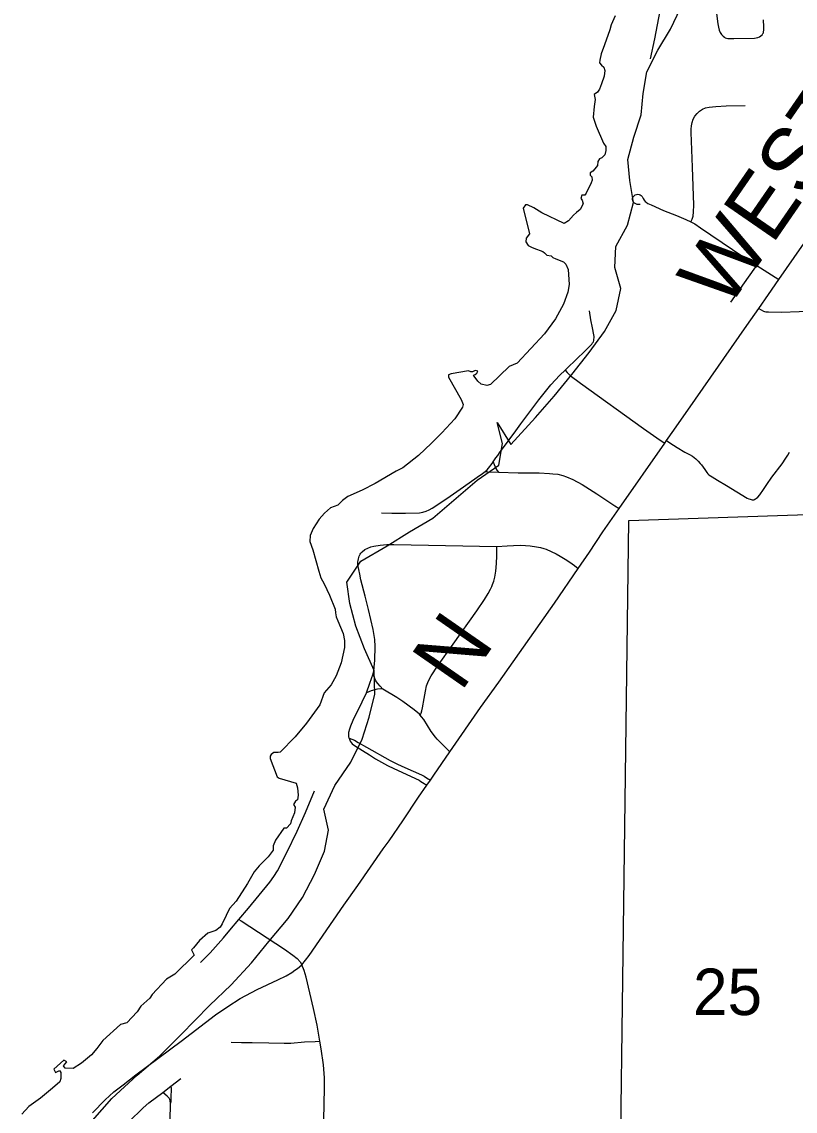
# Model space of a CAD drawing. Extents: x 63.4 to 97.4, y 0.4 to 22.4.
# Drawn here: x 67.176 to 67.874, y 18.029 to 19.011 of the extents above; entities that cross this region are included whole.
import ezdxf

# ---------------------------------------------------------------- set-up
doc = ezdxf.new("R2010")
doc.units = 0
for name, color, linetype in [('GM_X_County_Road', 7, 'Continuous'), ('GM_X_County_Road_Text', 7, 'Continuous'), ('GM_X_Major_Lake', 7, 'Continuous'), ('GM_X_Section', 7, 'Continuous'), ('GM_X_Section_Text', 7, 'Continuous'), ('GM_X_Township_Road', 7, 'Continuous'), ('SH_Cut_Line', 7, 'Continuous')]:
    doc.layers.add(name, color=color, linetype=linetype)

msp = doc.modelspace()

# ---------------------------------------------------------------- linework, layer by layer
at = {"layer": 'GM_X_County_Road'}
for p, q in [((67.71491, 18.57238), (67.75618, 18.63125)), ((67.75618, 18.63125), (67.75785, 18.63363))]:
    msp.add_line(p, q, dxfattribs=at)
for points in [[(67.71154, 19.0165), (67.70789, 19.00859), (67.70659, 19.00381), (67.70172, 18.99034), (67.69886, 18.98243), (67.69747, 18.97661), (67.69738, 18.9741), (67.69903, 18.97201), (67.70129, 18.97018), (67.70216, 18.96723), (67.70137, 18.96219), (67.69912, 18.95532), (67.69738, 18.95055), (67.69538, 18.94776), (67.69249, 18.94562), (67.6933, 18.94116), (67.6926, 18.93473), (67.69147, 18.92518), (67.69425, 18.91718), (67.70085, 18.9018), (67.70303, 18.89884), (67.70303, 18.89511), (67.70198, 18.89129), (67.69946, 18.88859), (67.69738, 18.88763), (67.69573, 18.88529), (67.69538, 18.88164), (67.69321, 18.87868), (67.69138, 18.87642), (67.68886, 18.87495), (67.68886, 18.87304), (67.69043, 18.87147), (67.69077, 18.86843), (67.68973, 18.86608), (67.68521, 18.8567), (67.68417, 18.85479), (67.68139, 18.85479), (67.68035, 18.85184), (67.68156, 18.85044), (67.68261, 18.84697), (67.67982, 18.84193), (67.67653, 18.83932), (67.67392, 18.83672), (67.6694, 18.83167), (67.6654, 18.82942), (67.64541, 18.83897), (67.63812, 18.84349), (67.63238, 18.84627), (67.63047, 18.84627), (67.62856, 18.84332), (67.63429, 18.82003), (67.63117, 18.81621), (67.63082, 18.81291), (67.63307, 18.8096), (67.63655, 18.80787), (67.64055, 18.8063), (67.64385, 18.80508), (67.64628, 18.80421), (67.64767, 18.80283), (67.64993, 18.80091), (67.65376, 18.80022), (67.65532, 18.79865), (67.65793, 18.79744), (67.66488, 18.79483), (67.66696, 18.79258), (67.66905, 18.78788), (67.67009, 18.77433), (67.66888, 18.76737), (67.66471, 18.75677), (67.65758, 18.74356), (67.64767, 18.72984), (67.62317, 18.70359), (67.61582, 18.70044), (67.59884, 18.6843), (67.59571, 18.68326), (67.59067, 18.68465), (67.58754, 18.68726), (67.58424, 18.6916), (67.58354, 18.69265), (67.58528, 18.69334), (67.58668, 18.69455), (67.58754, 18.69629), (67.58528, 18.69699), (67.58285, 18.69577), (67.58111, 18.69577), (67.57903, 18.69664), (67.56356, 18.69386), (67.56113, 18.69282), (67.56096, 18.69073), (67.57259, 18.67058), (67.57433, 18.66605), (67.57364, 18.6638), (67.56686, 18.65337), (67.55522, 18.64051), (67.54566, 18.6313), (67.53419, 18.62018), (67.51977, 18.60923), (67.51386, 18.6061), (67.49492, 18.59497), (67.48327, 18.58906), (67.47041, 18.58333), (67.46537, 18.57968), (67.4612, 18.57534), (67.45477, 18.5729), (67.44938, 18.56838), (67.44434, 18.56282), (67.43896, 18.55431), (67.43635, 18.54805), (67.436, 18.54284), (67.43878, 18.53519), (67.44417, 18.51608), (67.4459, 18.50982), (67.44904, 18.50443), (67.4539, 18.49418), (67.45877, 18.48184), (67.45915, 18.47853), (67.4599, 18.47471), (67.4612, 18.47124), (67.46607, 18.45977), (67.46728, 18.45334), (67.46728, 18.44725), (67.46415, 18.43335), (67.45981, 18.42171), (67.45529, 18.41354), (67.44904, 18.40642), (67.44504, 18.39547), (67.43305, 18.37896), (67.42279, 18.36662), (67.40924, 18.35271), (67.40732, 18.35254), (67.40368, 18.35254), (67.40124, 18.35063), (67.4002, 18.34907), (67.4002, 18.34715), (67.40646, 18.33047), (67.40837, 18.32942), (67.42366, 18.32491), (67.42488, 18.32074), (67.42557, 18.31413), (67.42488, 18.30979), (67.42314, 18.30857), (67.4214, 18.30562), (67.42279, 18.30318), (67.4221, 18.29797), (67.41914, 18.29084), (67.41845, 18.28807), (67.41497, 18.28442), (67.41271, 18.28442), (67.40509, 18.27356), (67.40298, 18.26826), (67.40281, 18.26443), (67.39846, 18.25852), (67.39045, 18.25034), (67.38577, 18.24497), (67.37965, 18.23449), (67.36944, 18.21838), (67.3637, 18.21195), (67.36058, 18.20569), (67.35693, 18.19804), (67.35519, 18.19492), (67.35119, 18.19196), (67.34389, 18.18953), (67.33636, 18.18307), (67.3312, 18.17649), (67.3293, 18.17459), (67.33155, 18.16989), (67.31417, 18.15269), (67.3067, 18.14816), (67.29367, 18.13444), (67.29175, 18.13096), (67.28359, 18.12384), (67.28028, 18.11862), (67.2709, 18.10889), (67.26534, 18.10733), (67.24918, 18.09273), (67.24379, 18.08561), (67.23893, 18.08004), (67.23006, 18.07257), (67.22263, 18.06771), (67.21546, 18.06805), (67.21372, 18.06996), (67.21685, 18.07361), (67.21407, 18.075), (67.20504, 18.06701), (67.2066, 18.06406), (67.21025, 18.06596), (67.21147, 18.06406), (67.21147, 18.05867), (67.21042, 18.05571), (67.20382, 18.04998), (67.19304, 18.04094), (67.18244, 18.03329), (67.17619, 18.02651)], [(67.85922, 18.77885), (67.87996, 18.80876), (67.89123, 18.82499)], [(67.84097, 18.75277), (67.84985, 18.76533), (67.85922, 18.77885)], [(67.75785, 18.63363), (67.7644, 18.64298), (67.7839, 18.67108), (67.83011, 18.73741), (67.84097, 18.75277)], [(67.67807, 18.51844), (67.68815, 18.53321), (67.70017, 18.55135), (67.71491, 18.57238)], [(67.56216, 18.35309), (67.59006, 18.39301), (67.6064, 18.41596), (67.65664, 18.48705), (67.67807, 18.51844)], [(67.54159, 18.32292), (67.5448, 18.32756), (67.54783, 18.33194), (67.56216, 18.35309)], [(67.42892, 18.16121), (67.43531, 18.16942), (67.46681, 18.21481), (67.47921, 18.2325), (67.5021, 18.26557), (67.50766, 18.27295), (67.51987, 18.29085), (67.53413, 18.31215), (67.54159, 18.32292)], [(67.44501, 18.09215), (67.44401, 18.09754), (67.44257, 18.10669), (67.43946, 18.12182), (67.43273, 18.15011), (67.43099, 18.15607), (67.42892, 18.16121)], [(67.44665, 17.90764), (67.44664, 17.91219), (67.44662, 17.93215), (67.44827, 18.00667), (67.44927, 18.0501), (67.44913, 18.05926), (67.44829, 18.07095), (67.44625, 18.0855), (67.44501, 18.09215)]]:
    msp.add_lwpolyline(points, dxfattribs=at)
at = {"layer": 'GM_X_Major_Lake'}
msp.add_lwpolyline([(67.23121, 18.01084), (67.25739, 18.04048), (67.28016, 18.06175), (67.30027, 18.07885), (67.31962, 18.09785), (67.34543, 18.12444), (67.36516, 18.14306), (67.38337, 18.16282), (67.39893, 18.18219), (67.41638, 18.20271), (67.42928, 18.22171), (67.44029, 18.2426), (67.44939, 18.2635), (67.4528, 18.28249), (67.44863, 18.30149), (67.45849, 18.32276), (67.47291, 18.34366), (67.48315, 18.36456), (67.4896, 18.38431), (67.49453, 18.40521), (67.49415, 18.42648), (67.48541, 18.44586), (67.47744, 18.46637), (67.47213, 18.48689), (67.46947, 18.50589), (67.48199, 18.52488), (67.5059, 18.53894), (67.52601, 18.55149), (67.54688, 18.56365), (67.5871, 18.59785), (67.60645, 18.61153), (67.60986, 18.63091), (67.60493, 18.64991), (67.61745, 18.63015), (67.63946, 18.65447), (67.65653, 18.67385), (67.67247, 18.69323), (67.68802, 18.71299), (67.70168, 18.73199), (67.71231, 18.75099), (67.71648, 18.77075), (67.71116, 18.78975), (67.71192, 18.80875), (67.72254, 18.82775), (67.72785, 18.84827), (67.72481, 18.86803), (67.72291, 18.88703), (67.72821, 18.90717), (67.73504, 18.92731), (67.73656, 18.94669), (67.73997, 18.96607), (67.74983, 18.98546), (67.76121, 19.00446), (67.77031, 19.02346)], dxfattribs=at)
at = {"layer": 'GM_X_Section'}
msp.add_lwpolyline([(67.89376, 18.5672), (67.92566, 17.57266), (67.71099, 17.57298), (67.72391, 18.56172)], close=True, dxfattribs=at)
at = {"layer": 'GM_X_Township_Road'}
for p, q in [((67.30355, 18.046), (67.31071, 18.05163)), ((67.31071, 18.05163), (67.31959, 18.05859))]:
    msp.add_line(p, q, dxfattribs=at)
for points in [[(67.74342, 18.97772), (67.74726, 18.99596), (67.75087, 19.01485), (67.75214, 19.02052), (67.75306, 19.0234), (67.75433, 19.02618), (67.75572, 19.02883), (67.75745, 19.03172), (67.75929, 19.03403), (67.76172, 19.03657), (67.76426, 19.03865), (67.76657, 19.04027), (67.76923, 19.04211), (67.77165, 19.04373), (67.77396, 19.04604), (67.7757, 19.04847), (67.77851, 19.05287)], [(67.8027, 19.0186), (67.8041, 19.00932), (67.80461, 19.00627), (67.80524, 19.00369), (67.80608, 19.00157), (67.80731, 18.99973), (67.80885, 18.9982), (67.80997, 18.99731), (67.81078, 18.9968), (67.81177, 18.99645), (67.81294, 18.99624), (67.8143, 18.99624), (67.81836, 18.99615), (67.83707, 18.99642), (67.83865, 18.99665), (67.84, 18.99704), (67.84169, 18.99777), (67.84277, 18.99858), (67.84392, 18.99951), (67.84477, 19.00054), (67.84511, 19.00123), (67.84535, 19.00204), (67.84555, 19.00351), (67.84568, 19.00666), (67.84533, 19.01284)], [(67.77957, 18.83099), (67.78089, 18.8334), (67.78176, 18.83592), (67.78222, 18.83978), (67.78239, 18.84598), (67.78133, 18.88018), (67.78073, 18.89571), (67.77997, 18.91125), (67.78002, 18.91436), (67.7803, 18.91745), (67.78092, 18.9205), (67.78194, 18.92344), (67.78339, 18.92619), (67.78528, 18.92865), (67.78757, 18.93075), (67.7902, 18.93238), (67.79307, 18.93354), (67.7961, 18.93427), (67.80229, 18.93487), (67.81162, 18.93539), (67.82861, 18.93567)], [(67.73396, 18.84655), (67.73264, 18.84648), (67.73133, 18.84655), (67.72996, 18.84713), (67.72892, 18.84776), (67.72816, 18.8484), (67.7276, 18.84907), (67.72733, 18.84994), (67.7272, 18.85077), (67.7272, 18.85217), (67.72764, 18.85344), (67.72852, 18.8544), (67.72957, 18.85511), (67.73062, 18.8555), (67.73185, 18.85572), (67.73299, 18.85555), (67.73408, 18.85511), (67.735, 18.8545), (67.73583, 18.85357), (67.7368, 18.85187), (67.73766, 18.85027), (67.73851, 18.84923), (67.73951, 18.84846), (67.741, 18.84748), (67.7439, 18.84608), (67.75514, 18.8411), (67.76663, 18.83649), (67.77509, 18.83287), (67.77957, 18.83099)], [(67.77957, 18.83099), (67.78319, 18.82902), (67.78846, 18.82557), (67.83689, 18.79272), (67.83908, 18.79136)], [(67.81587, 18.75853), (67.8368, 18.78814), (67.83908, 18.79136)], [(67.83908, 18.79136), (67.8526, 18.78296), (67.85922, 18.77885)], [(67.66624, 18.69722), (67.66813, 18.69909), (67.68448, 18.71443), (67.68898, 18.719), (67.69028, 18.72046), (67.69112, 18.72167), (67.69175, 18.72266), (67.69211, 18.72386), (67.69232, 18.72512), (67.69243, 18.72642), (67.69237, 18.72741), (67.69216, 18.72898), (67.69101, 18.73525), (67.6896, 18.74246), (67.6883, 18.75074)], [(67.84097, 18.75277), (67.84304, 18.75144), (67.84524, 18.7504), (67.84615, 18.75011), (67.84731, 18.74978), (67.84971, 18.74958), (67.86139, 18.74947), (67.87727, 18.74991), (67.90542, 18.7507), (67.90855, 18.7507), (67.91164, 18.75041), (67.91316, 18.74996), (67.91408, 18.74952), (67.91505, 18.749)], [(67.60152, 18.61454), (67.60393, 18.61809), (67.6055, 18.62034), (67.60711, 18.62253), (67.61589, 18.6344), (67.6218, 18.6425), (67.6265, 18.64865), (67.64246, 18.67038), (67.65345, 18.68382), (67.6615, 18.69251), (67.66624, 18.69722)], [(67.66624, 18.69722), (67.66806, 18.69513), (67.67083, 18.69246), (67.68006, 18.68539), (67.73689, 18.64457), (67.75193, 18.63418), (67.75618, 18.63125)], [(67.75785, 18.63363), (67.7609, 18.63167), (67.76751, 18.62742), (67.77442, 18.62337), (67.77855, 18.621), (67.7811, 18.61948), (67.78273, 18.61827), (67.78425, 18.61712), (67.78625, 18.61524), (67.78813, 18.61312), (67.78937, 18.61168), (67.7922, 18.60754), (67.79407, 18.60487), (67.79499, 18.60384), (67.79607, 18.60287), (67.79881, 18.60087), (67.80369, 18.59788), (67.81186, 18.59322), (67.83055, 18.58184), (67.83203, 18.58117), (67.83319, 18.58075), (67.83408, 18.58047), (67.83488, 18.58031), (67.83561, 18.5803), (67.83648, 18.5804)], [(67.83648, 18.5804), (67.83744, 18.58075), (67.83805, 18.58114), (67.83901, 18.58178), (67.84005, 18.58272), (67.84207, 18.58488), (67.84525, 18.58948), (67.84828, 18.59403), (67.85289, 18.6007), (67.86212, 18.61272), (67.86553, 18.61782), (67.86732, 18.62065), (67.86866, 18.62327)], [(67.59419, 18.60568), (67.59609, 18.60743), (67.59724, 18.60885), (67.60053, 18.61308), (67.60152, 18.61454)], [(67.60152, 18.61454), (67.60226, 18.61223), (67.60309, 18.60994), (67.60382, 18.60845), (67.60465, 18.60706), (67.60615, 18.60523)], [(67.50074, 18.56852), (67.50991, 18.56838), (67.52235, 18.56821), (67.53482, 18.56857), (67.53789, 18.56905), (67.54085, 18.5699), (67.5437, 18.57114), (67.54643, 18.57267), (67.55951, 18.5816), (67.57478, 18.59202), (67.587, 18.60064), (67.59192, 18.60399), (67.59419, 18.60568)], [(67.59419, 18.60568), (67.59668, 18.60559), (67.60615, 18.60523)], [(67.60615, 18.60523), (67.62407, 18.60455), (67.64279, 18.60447), (67.65223, 18.60405), (67.65534, 18.60377), (67.65961, 18.60325), (67.66413, 18.60212), (67.66751, 18.60103), (67.67328, 18.59852), (67.68155, 18.59397), (67.69483, 18.58573), (67.71114, 18.57489), (67.71491, 18.57238)], [(67.4932, 18.42344), (67.49366, 18.42626), (67.49417, 18.42955), (67.49452, 18.43573), (67.49504, 18.44806), (67.49462, 18.45423), (67.49307, 18.46338), (67.48901, 18.48148), (67.48584, 18.49339), (67.48214, 18.50818), (67.48099, 18.51318), (67.48011, 18.51749), (67.47962, 18.52018), (67.47938, 18.52247), (67.47945, 18.52437), (67.4796, 18.52561), (67.47981, 18.52715), (67.48055, 18.52935), (67.48135, 18.53117), (67.48216, 18.5322), (67.48318, 18.5333)], [(67.48318, 18.5333), (67.48571, 18.53534), (67.48846, 18.53677), (67.4911, 18.53782), (67.49375, 18.53854), (67.49946, 18.53948), (67.50555, 18.53989), (67.51177, 18.53992), (67.54295, 18.53936), (67.55854, 18.5392), (67.57416, 18.5389), (67.60404, 18.53829), (67.60468, 18.53832)], [(67.53542, 18.38624), (67.53635, 18.38799), (67.53718, 18.39019), (67.53771, 18.39283), (67.53906, 18.40126), (67.54031, 18.40784), (67.54126, 18.41255), (67.54293, 18.41704), (67.54543, 18.42154), (67.55128, 18.43042), (67.56537, 18.45005), (67.5866, 18.48007), (67.59349, 18.49041), (67.59694, 18.49584), (67.59903, 18.49961), (67.60007, 18.50211), (67.60081, 18.50389), (67.60185, 18.50682), (67.60279, 18.51048), (67.60373, 18.51581), (67.60436, 18.52291), (67.60465, 18.52971), (67.60467, 18.53555), (67.60468, 18.53832)], [(67.60468, 18.53832), (67.61391, 18.5388), (67.61969, 18.53902), (67.62635, 18.53925), (67.63469, 18.53866), (67.6404, 18.53785), (67.64398, 18.53719), (67.6472, 18.53639), (67.64925, 18.53573), (67.65379, 18.53368), (67.65825, 18.53149), (67.66191, 18.52959), (67.66647, 18.52677), (67.67066, 18.52399), (67.67471, 18.52096), (67.67807, 18.51844)], [(67.48702, 18.40638), (67.49026, 18.41485), (67.4932, 18.42344)], [(67.50183, 18.4096), (67.49942, 18.41227), (67.49734, 18.41462), (67.49627, 18.41622), (67.4954, 18.41762), (67.49427, 18.4201), (67.49373, 18.42144), (67.4932, 18.42344)], [(67.47151, 18.36529), (67.47121, 18.36679), (67.47113, 18.36833), (67.47135, 18.37096), (67.47208, 18.37389), (67.47292, 18.37644), (67.4751, 18.3817), (67.48321, 18.3981), (67.48702, 18.40638)], [(67.50183, 18.4096), (67.49975, 18.4098), (67.49714, 18.4096), (67.49454, 18.40902), (67.49135, 18.40799), (67.48702, 18.40638)], [(67.53542, 18.38624), (67.53481, 18.38691), (67.53003, 18.39087), (67.51986, 18.39844), (67.51463, 18.40194), (67.50183, 18.4096)], [(67.56216, 18.35309), (67.55662, 18.35894), (67.55401, 18.36145), (67.55098, 18.36448), (67.54928, 18.36635), (67.54547, 18.37151), (67.53873, 18.38224), (67.53687, 18.38467), (67.53542, 18.38624)], [(67.47151, 18.36529), (67.47245, 18.36275), (67.47325, 18.36145), (67.47425, 18.36033), (67.47728, 18.35809), (67.48994, 18.35033), (67.49535, 18.34689), (67.50069, 18.34373), (67.50618, 18.3409), (67.51187, 18.33814), (67.5345, 18.32743), (67.53618, 18.32649), (67.53779, 18.32546), (67.54159, 18.32292)], [(67.47151, 18.36529), (67.47391, 18.36459), (67.47618, 18.36364), (67.4797, 18.36164), (67.48701, 18.35743), (67.50837, 18.34543), (67.51496, 18.34207), (67.52184, 18.33885), (67.53681, 18.33235), (67.5391, 18.3311), (67.54122, 18.32978), (67.5448, 18.32756)], [(67.37204, 18.20202), (67.38059, 18.21222), (67.40009, 18.23563), (67.4036, 18.24058), (67.40671, 18.24584), (67.41513, 18.26224), (67.42472, 18.28146), (67.43204, 18.29847), (67.44023, 18.31781)], [(67.33753, 18.16316), (67.3462, 18.17184), (67.35821, 18.18551), (67.3639, 18.1923), (67.37204, 18.20202)], [(67.37204, 18.20202), (67.37418, 18.20062), (67.41306, 18.17512), (67.42077, 18.16988), (67.42471, 18.16677), (67.42718, 18.16386), (67.42892, 18.16121)], [(67.24012, 18.02781), (67.25154, 18.03938), (67.2591, 18.04649), (67.26758, 18.05285), (67.27907, 18.06178), (67.32008, 18.09219), (67.35094, 18.11596), (67.36213, 18.12367), (67.37333, 18.13079), (67.38861, 18.13881), (67.40707, 18.14759), (67.41476, 18.15127), (67.41973, 18.15425), (67.42263, 18.15616), (67.42487, 18.15773), (67.42892, 18.16121)], [(67.36496, 18.09133), (67.37427, 18.0911), (67.3841, 18.09098), (67.39916, 18.09069), (67.41279, 18.09033), (67.41888, 18.0904), (67.4313, 18.09153), (67.44072, 18.09196), (67.44501, 18.09215)], [(67.31031, 18.03595), (67.31083, 18.03788), (67.31102, 18.03986), (67.31107, 18.04235), (67.3112, 18.04833), (67.31111, 18.04996), (67.31096, 18.05079), (67.31071, 18.05163)], [(67.25969, 18.00673), (67.27276, 18.01965), (67.28561, 18.03229), (67.2907, 18.03675), (67.30355, 18.046)], [(67.31031, 18.03595), (67.31001, 18.03838), (67.30971, 18.03973), (67.30904, 18.04086), (67.30738, 18.0427), (67.30355, 18.046)], [(67.30888, 17.97377), (67.30866, 17.98163), (67.30866, 17.9896), (67.30917, 18.00441), (67.31033, 18.03197), (67.31031, 18.03595)]]:
    msp.add_lwpolyline(points, dxfattribs=at)
at = {"layer": 'SH_Cut_Line'}
msp.add_lwpolyline([(67.71154, 19.0165), (67.70789, 19.00859), (67.70659, 19.00381), (67.70172, 18.99034), (67.69886, 18.98243), (67.69747, 18.97661), (67.69738, 18.9741), (67.69903, 18.97201), (67.70129, 18.97018), (67.70216, 18.96723), (67.70137, 18.96219), (67.69912, 18.95532), (67.69738, 18.95055), (67.69538, 18.94776), (67.69249, 18.94562), (67.6933, 18.94116), (67.6926, 18.93473), (67.69147, 18.92518), (67.69425, 18.91718), (67.70085, 18.9018), (67.70303, 18.89884), (67.70303, 18.89511), (67.70198, 18.89129), (67.69946, 18.88859), (67.69738, 18.88763), (67.69573, 18.88529), (67.69538, 18.88164), (67.69321, 18.87868), (67.69138, 18.87642), (67.68886, 18.87495), (67.68886, 18.87304), (67.69043, 18.87147), (67.69077, 18.86843), (67.68973, 18.86608), (67.68521, 18.8567), (67.68417, 18.85479), (67.68139, 18.85479), (67.68035, 18.85184), (67.68156, 18.85044), (67.68261, 18.84697), (67.67982, 18.84193), (67.67653, 18.83932), (67.67392, 18.83672), (67.6694, 18.83167), (67.6654, 18.82942), (67.64541, 18.83897), (67.63812, 18.84349), (67.63238, 18.84627), (67.63047, 18.84627), (67.62856, 18.84332), (67.63429, 18.82003), (67.63117, 18.81621), (67.63082, 18.81291), (67.63307, 18.8096), (67.63655, 18.80787), (67.64055, 18.8063), (67.64385, 18.80508), (67.64628, 18.80421), (67.64767, 18.80283), (67.64993, 18.80091), (67.65376, 18.80022), (67.65532, 18.79865), (67.65793, 18.79744), (67.66488, 18.79483), (67.66696, 18.79258), (67.66905, 18.78788), (67.67009, 18.77433), (67.66888, 18.76737), (67.66471, 18.75677), (67.65758, 18.74356), (67.64767, 18.72984), (67.62317, 18.70359), (67.61582, 18.70044), (67.59884, 18.6843), (67.59571, 18.68326), (67.59067, 18.68465), (67.58754, 18.68726), (67.58424, 18.6916), (67.58354, 18.69265), (67.58528, 18.69334), (67.58668, 18.69455), (67.58754, 18.69629), (67.58528, 18.69699), (67.58285, 18.69577), (67.58111, 18.69577), (67.57903, 18.69664), (67.56356, 18.69386), (67.56113, 18.69282), (67.56096, 18.69073), (67.57259, 18.67058), (67.57433, 18.66605), (67.57364, 18.6638), (67.56686, 18.65337), (67.55522, 18.64051), (67.54566, 18.6313), (67.53419, 18.62018), (67.51977, 18.60923), (67.51386, 18.6061), (67.49492, 18.59497), (67.48327, 18.58906), (67.47041, 18.58333), (67.46537, 18.57968), (67.4612, 18.57534), (67.45477, 18.5729), (67.44938, 18.56838), (67.44434, 18.56282), (67.43896, 18.55431), (67.43635, 18.54805), (67.436, 18.54284), (67.43878, 18.53519), (67.44417, 18.51608), (67.4459, 18.50982), (67.44904, 18.50443), (67.4539, 18.49418), (67.45877, 18.48184), (67.45915, 18.47853), (67.4599, 18.47471), (67.4612, 18.47124), (67.46607, 18.45977), (67.46728, 18.45334), (67.46728, 18.44725), (67.46415, 18.43335), (67.45981, 18.42171), (67.45529, 18.41354), (67.44904, 18.40642), (67.44504, 18.39547), (67.43305, 18.37896), (67.42279, 18.36662), (67.40924, 18.35271), (67.40732, 18.35254), (67.40368, 18.35254), (67.40124, 18.35063), (67.4002, 18.34907), (67.4002, 18.34715), (67.40646, 18.33047), (67.40837, 18.32942), (67.42366, 18.32491), (67.42488, 18.32074), (67.42557, 18.31413), (67.42488, 18.30979), (67.42314, 18.30857), (67.4214, 18.30562), (67.42279, 18.30318), (67.4221, 18.29797), (67.41914, 18.29084), (67.41845, 18.28807), (67.41497, 18.28442), (67.41271, 18.28442), (67.40509, 18.27356), (67.40298, 18.26826), (67.40281, 18.26443), (67.39846, 18.25852), (67.39045, 18.25034), (67.38577, 18.24497), (67.37965, 18.23449), (67.36944, 18.21838), (67.3637, 18.21195), (67.36058, 18.20569), (67.35693, 18.19804), (67.35519, 18.19492), (67.35119, 18.19196), (67.34389, 18.18953), (67.33636, 18.18307), (67.3312, 18.17649), (67.3293, 18.17459), (67.33155, 18.16989), (67.31417, 18.15269), (67.3067, 18.14816), (67.29367, 18.13444), (67.29175, 18.13096), (67.28359, 18.12384), (67.28028, 18.11862), (67.2709, 18.10889), (67.26534, 18.10733), (67.24918, 18.09273), (67.24379, 18.08561), (67.23893, 18.08004), (67.23006, 18.07257), (67.22263, 18.06771), (67.21546, 18.06805), (67.21372, 18.06996), (67.21685, 18.07361), (67.21407, 18.075), (67.20504, 18.06701), (67.2066, 18.06406), (67.21025, 18.06596), (67.21147, 18.06406), (67.21147, 18.05867), (67.21042, 18.05571), (67.20382, 18.04998), (67.19304, 18.04094), (67.18244, 18.03329), (67.17619, 18.02651)], dxfattribs=at)

# ---------------------------------------------------------------- texts
at = {"layer": 'GM_X_County_Road_Text'}
for s, height, rotation, p in [('WEST', 0.056818, 55.40097, (67.81218, 18.75032)), ('N', 0.05682, 55.24064, (67.57209, 18.40599))]:
    msp.add_text(s, height=height, rotation=rotation, dxfattribs=at).set_placement(p)
at = {"layer": 'GM_X_Section_Text'}
msp.add_text('25', height=0.041856, rotation=0.00001, dxfattribs=at).set_placement((67.78169, 18.11581))

doc.saveas('drawing.dxf')
